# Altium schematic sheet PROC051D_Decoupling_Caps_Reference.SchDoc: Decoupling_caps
size 431 x 279 mm; Date: Not shown in title block; ApprovedBy: Not shown in title block; CheckedBy: Not shown in title block; Author: Not shown in title block; CompanyName: Not shown in title block; Engineer: Not shown in title block; Organization: Not shown in title block; Address1: Not shown in title block; Address2: Not shown in title block; Address3: Not shown in title block; Address4: Not shown in title block; DocumentNumber: 3; Revision: Use project parameter SCH_Rev; SheetNumber: 3; SheetTotal: 16; PageSetup: Record=PageOptions¦CenterHorizontal=True¦CenterVertical=True¦PrintScale=1.00¦XCorrection=1.00¦YCorrection=1.00¦PrintKind=0¦BorderSize=5000000¦LeftOffset=0¦BottomOffset=0¦Orientation=2¦PaperLength=1000¦PaperWidth=1000¦Scale=100¦PaperSource=15¦PrintQuality=600¦MediaType=1¦DitherType=10¦PaperKind=Letter¦PrintScaleMode=1
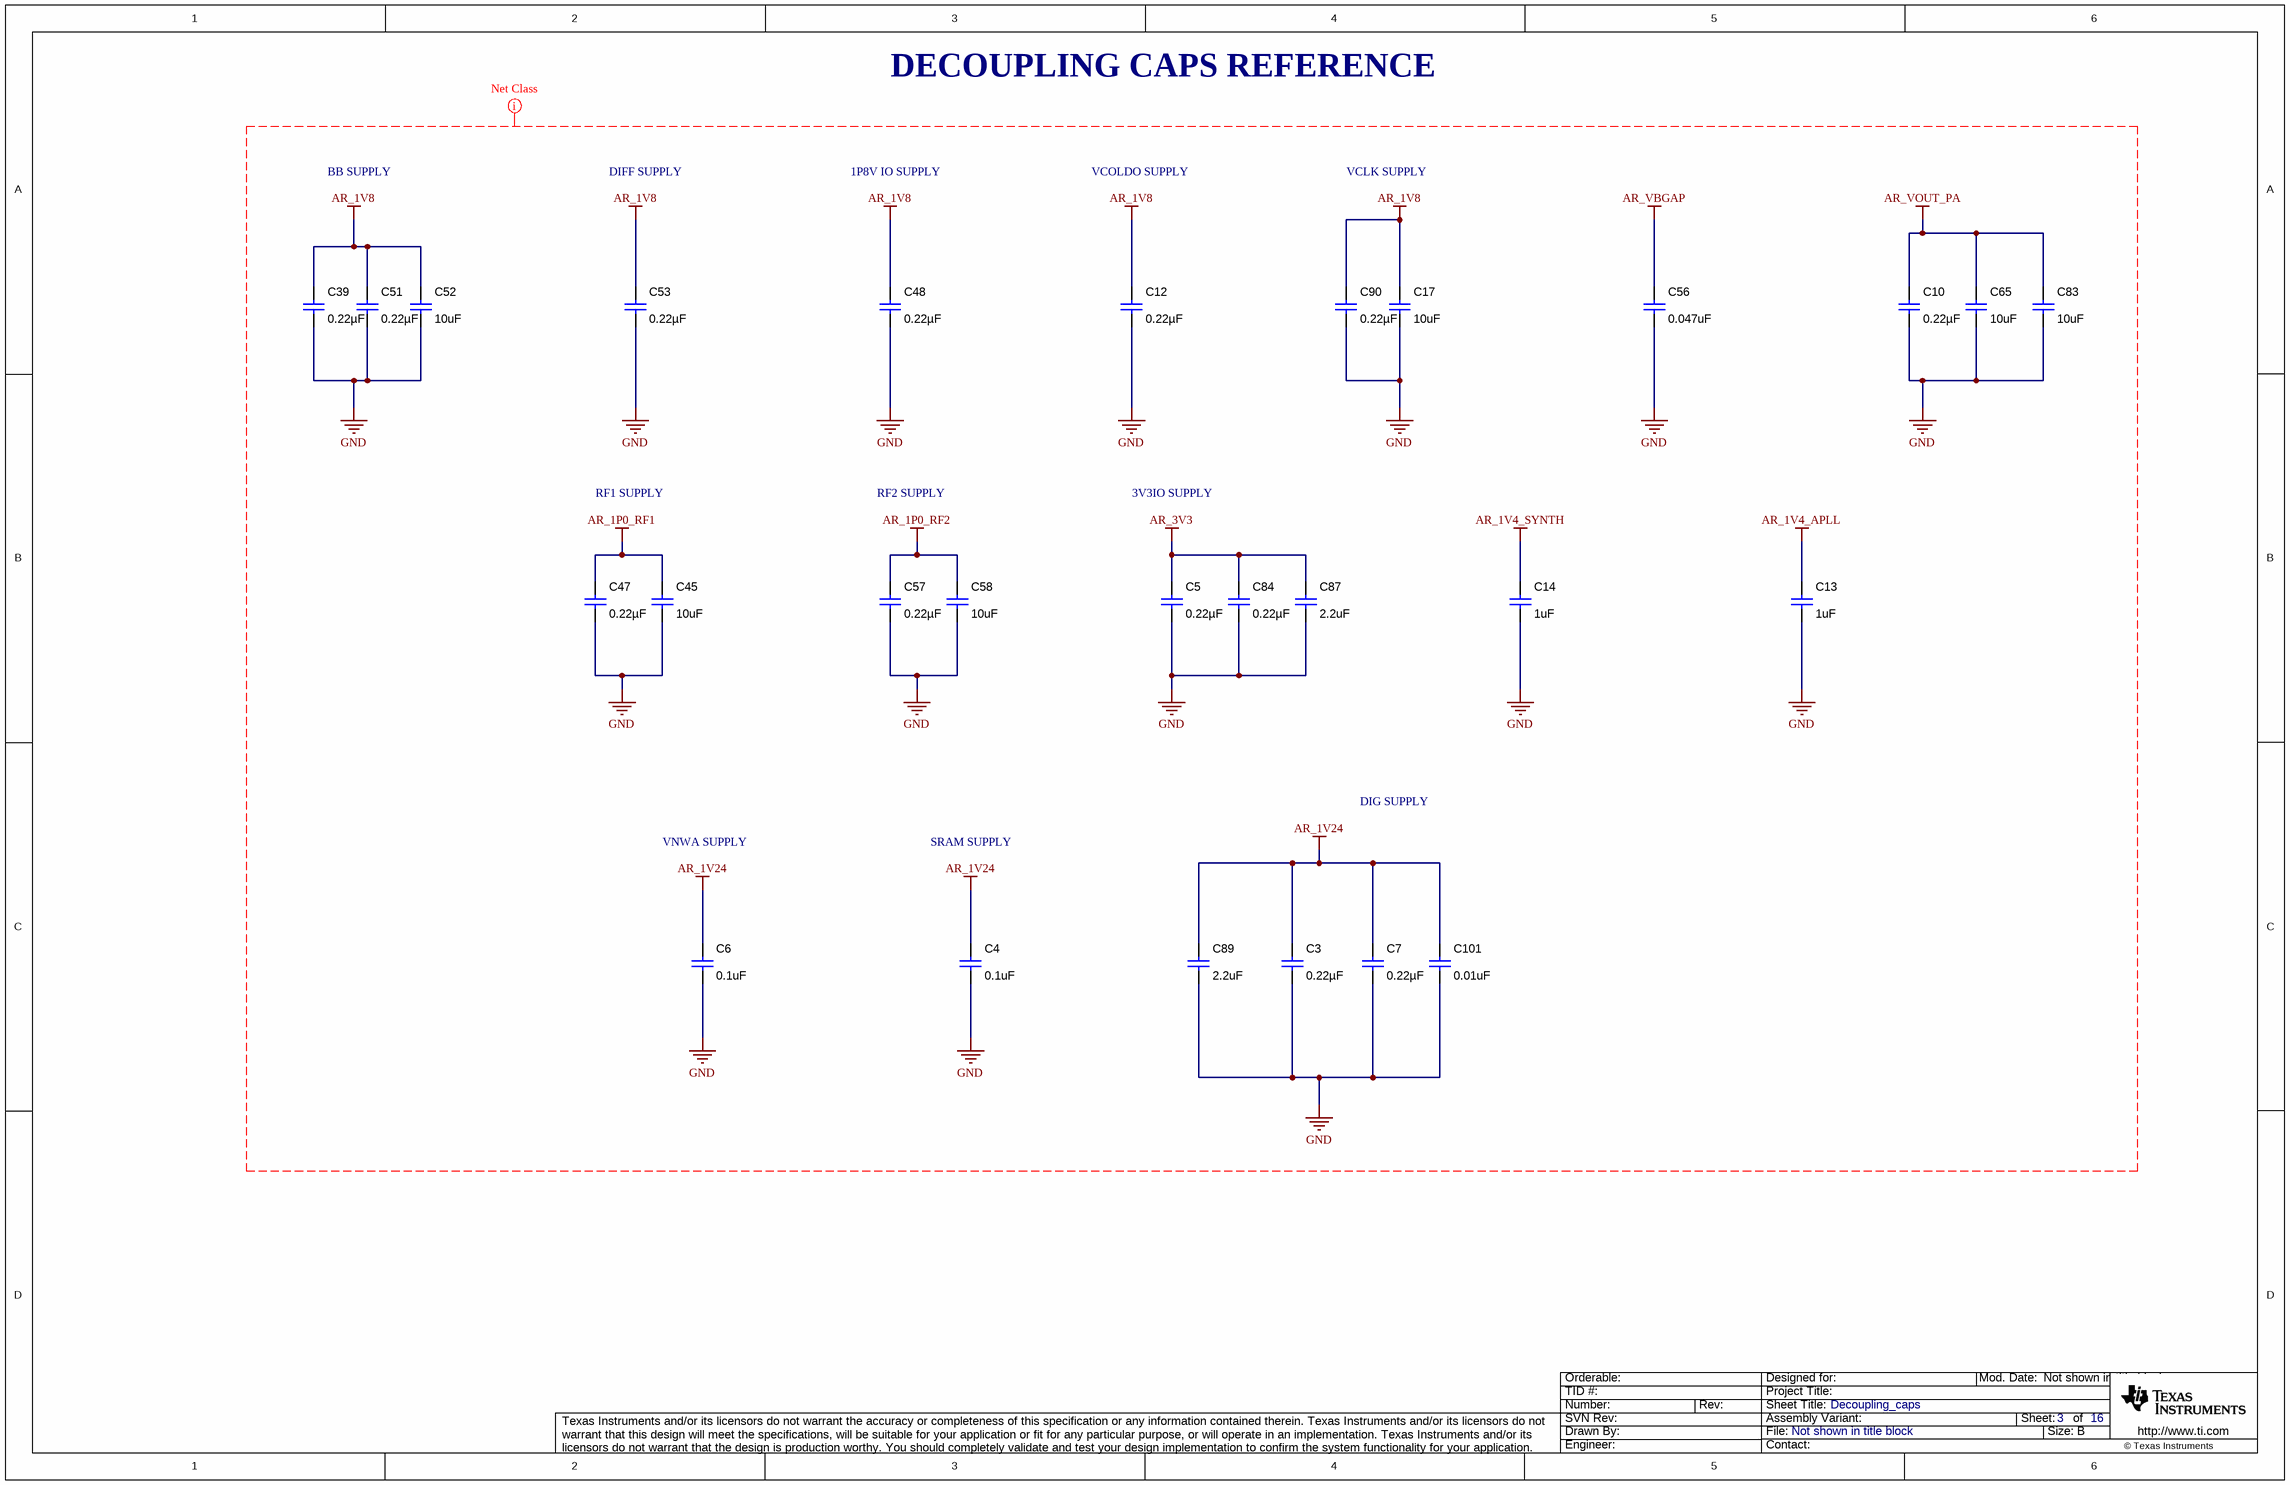
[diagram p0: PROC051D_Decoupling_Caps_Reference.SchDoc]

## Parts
C3  ValueDisplayed: 0.22µF  [0402L]  (hidden comment: GCM155R71C224KE02D)
C4  ValueDisplayed: 0.1uF  [0402L]  (hidden comment: GCM155R71C104KA55D)
C5  ValueDisplayed: 0.22µF  [0402L]  (hidden comment: GCM155R71C224KE02D)
C6  ValueDisplayed: 0.1uF  [0402L]  (hidden comment: GCM155R71C104KA55D)
C7  ValueDisplayed: 0.22µF  [0402L]  (hidden comment: GCM155R71C224KE02D)
C10  ValueDisplayed: 0.22µF  [0402L]  (hidden comment: GCM155R71C224KE02D)
C12  ValueDisplayed: 0.22µF  [0402L]  (hidden comment: GCM155R71C224KE02D)
C13  ValueDisplayed: 1uF  [0603]  (hidden comment: GCM188R71C105KA64D)
C14  ValueDisplayed: 1uF  [0603]  (hidden comment: GCM188R71C105KA64D)
C17  ValueDisplayed: 10uF  [0805_HV]  (hidden comment: GCM21BR71A106KE22L)
C39  ValueDisplayed: 0.22µF  [0402L]  (hidden comment: GCM155R71C224KE02D)
C45  ValueDisplayed: 10uF  [0805_HV]  (hidden comment: GCM21BR71A106KE22L)
C47  ValueDisplayed: 0.22µF  [0402L]  (hidden comment: GCM155R71C224KE02D)
C48  ValueDisplayed: 0.22µF  [0402L]  (hidden comment: GCM155R71C224KE02D)
C51  ValueDisplayed: 0.22µF  [0402L]  (hidden comment: GCM155R71C224KE02D)
C52  ValueDisplayed: 10uF  [0805_HV]  (hidden comment: GCM21BR71A106KE22L)
C53  ValueDisplayed: 0.22µF  [0402L]  (hidden comment: GCM155R71C224KE02D)
C56  ValueDisplayed: 0.047uF  [0402]  (hidden comment: CGA2B3X7R1H473K050BB)
C57  ValueDisplayed: 0.22µF  [0402L]  (hidden comment: GCM155R71C224KE02D)
C58  ValueDisplayed: 10uF  [0805_HV]  (hidden comment: GCM21BR71A106KE22L)
C65  ValueDisplayed: 10uF  [0805_HV]  (hidden comment: GCM21BR71A106KE22L)
C83  ValueDisplayed: 10uF  [0805_HV]  (hidden comment: GCM21BR71A106KE22L)
C84  ValueDisplayed: 0.22µF  [0402L]  (hidden comment: GCM155R71C224KE02D)
C87  ValueDisplayed: 2.2uF  [0603]  (hidden comment: GCM188R70J225KE22D)
C89  ValueDisplayed: 2.2uF  [0603]  (hidden comment: GCM188R70J225KE22D)
C90  ValueDisplayed: 0.22µF  [0402L]  (hidden comment: GCM155R71C224KE02D)
C101  ValueDisplayed: 0.01uF  [0402L]  (hidden comment: GCM155R71E103KA37D)

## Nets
AR_1P0_RF1: C45.2 C47.2
AR_1P0_RF2: C57.2 C58.2
AR_1V4_APLL: C13.2
AR_1V4_SYNTH: C14.2
AR_1V8: C12.2 C17.2 C39.2 C48.2 C51.2 C52.2 C53.2 C90.2
AR_1V24: C3.2 C4.2 C6.2 C7.2 C89.2 C101.1
AR_3V3: C5.2 C84.2 C87.2
AR_VBGAP: C56.1
AR_VOUT_PA: C10.2 C65.2 C83.2
GND: C3.1 C4.1 C5.1 C6.1 C7.1 C10.1 C12.1 C13.1 C14.1 C17.1 C39.1 C45.1 C47.1 C48.1 C51.1 C52.1 C53.1 C56.2 C57.1 C58.1 C65.1 C83.1 C84.1 C87.1 C89.1 C90.1 C101.2

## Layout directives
net class PWR: AR_1P0_RF1, AR_1P0_RF2, AR_1V4_APLL, AR_1V4_SYNTH, AR_1V8, AR_1V24, AR_3V3, AR_VBGAP, AR_VOUT_PA, GND

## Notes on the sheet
- DECOUPLING CAPS REFERENCE
- BB SUPPLY
- DIFF SUPPLY
- 1P8V IO SUPPLY
- VCOLDO SUPPLY
- VCLK SUPPLY
- RF1 SUPPLY
- RF2 SUPPLY
- 3V3IO SUPPLY
- DIG SUPPLY
- VNWA SUPPLY
- SRAM SUPPLY

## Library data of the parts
C3 C5 C7 C10 C12 C39 C47 C48 C51 C53 C57 C84 C90 = CMP-0078265-1: CAP, CERM, 0.22 µF, 16 V,+/- 10%, X7R, AEC-Q200 Grade 1, 0402; Manufacturer: MuRata; TaMin_C: -55°C; Polarized: N; SizeAreaWB_mm2: 3; U/M: EA; Value: 0.22uF; TaMax_C: 125°C; SizeZ_mm: 0.6; SizeX_mm: 1; SizeY_mm: 0.5; Cap_Case: 0402; Value2: 16V; CompType: Capacitor; AEC Qualified: Y; Cap_F: 220nF; AEC Category: Q200
C4 = CMP-0006351-2: CAP, CERM, 0.1 uF, 16 V, +/- 10%, X7R, 0402; Manufacturer: MuRata; TaMin_C: -55°C; Polarized: N; SizeAreaWB_mm2: 3; Value1: Unknown; U/M: EA; Value: 0.1uF; TaMax_C: 125°C; SizeZ_mm: 0.6; SizeX_mm: 1; SizeY_mm: 0.5; Cap_Case: 0402; Value2: 16V; CompType: Capacitor; Cap_F: 100nF; AEC Category: Q200
C6 = CMP-0006351-2: CAP, CERM, 0.1 uF, 16 V, +/- 10%, X7R, 0402; Manufacturer: MuRata; TaMin_C: -55°C; Polarized: N; SizeAreaWB_mm2: 3; Value1: Unknown; U/M: EA; Value: 0.1uF; TaMax_C: 125°C; SizeZ_mm: 0.6; SizeX_mm: 1; SizeY_mm: 0.5; Cap_Case: 0402; Value2: 16V; Cap_F: 100nF; AEC Category: Q200
C13 = CMP-0007136-5: CAP, CERM, 1 uF, 16 V, +/- 10%, X7R, AEC-Q200 Grade 1, 0603; Manufacturer: MuRata; TaMin_C: -55°C; Polarized: N; SizeAreaWB_mm2: 4.68; Value1: Unknown; U/M: EA; Value: 1uF; TaMax_C: 125°C; SizeZ_mm: 1; SizeX_mm: 1.6; SizeY_mm: 0.8; Value2: 16V; SizeArea_mm2: 1.28; AEC Qualified: Y; Cap_F: 1µF; AEC Category: Q200
C14 = CMP-0007136-5: CAP, CERM, 1 uF, 16 V, +/- 10%, X7R, AEC-Q200 Grade 1, 0603; Manufacturer: MuRata; TaMin_C: -55°C; Polarized: N; SizeAreaWB_mm2: 4.68; Value1: Unknown; U/M: EA; Value: 1uF; TaMax_C: 125°C; SizeZ_mm: 1; SizeX_mm: 1.6; SizeY_mm: 0.8; Value2: 16V; SizeArea_mm2: 1.28; CompType: Capacitor; AEC Qualified: Y; Cap_F: 1µF; AEC Category: Q200
C17 C45 C52 C58 C65 C83 = CMP-0008017-2: CAP, CERM, 10 uF, 10 V, +/- 10%, X7R, 0805; Manufacturer: MuRata; TaMin_C: -55°C; Polarized: N; SizeAreaWB_mm2: 6.75; Value1: Unknown; U/M: EA; Value: 10uF; TaMax_C: 125°C; SizeZ_mm: 1.45; SizeX_mm: 2; SizeY_mm: 1.25; Cap_Case: 0805; Value2: 10V; SizeArea_mm2: 2.5; CompType: Capacitor; Cap_F: 10µF; AEC Category: Q200
C56 = CMP-0006330-2: CAP, CERM, 0.047 uF, 50 V, +/- 10%, X7R, AEC-Q200 Grade 1, 0402; Manufacturer: TDK; TaMin_C: -55°C; ESR_ohm: 0.06407; Polarized: N; SizeAreaWB_mm2: 3; Value1: 0.06407 ohm; U/M: EA; TaMax_C: 125°C; SizeZ_mm: 0.6; SizeX_mm: 1; SizeY_mm: 0.5; Value2: 50V; AEC Qualified: Y; Cap_F: 47nF; IRMS_A: 646.122mA; AEC Category: Q200
C87 C89 = CMP-0007134-5: CAP, CERM, 2.2 uF, 6.3 V, +/- 10%, X7R, AEC-Q200 Grade 1, 0603; Manufacturer: MuRata; TaMin_C: -55°C; Polarized: N; SizeAreaWB_mm2: 4.68; Value1: Unknown; U/M: EA; Value: 2.2uF; TaMax_C: 125°C; SizeZ_mm: 1; SizeX_mm: 1.6; SizeY_mm: 0.8; Value2: 6.3V; SizeArea_mm2: 1.28; AEC Qualified: Y; Cap_F: 2.2µF; AEC Category: Q200
C101 = CMP-0006352-2: CAP, CERM, 0.01 uF, 25 V, +/- 10%, X7R, 0402; Manufacturer: MuRata; TaMin_C: -55°C; Polarized: N; SizeAreaWB_mm2: 3; Value1: Unknown; U/M: EA; Value: 0.01uF; TaMax_C: 125°C; SizeZ_mm: 0.6; SizeX_mm: 1; SizeY_mm: 0.5; Cap_Case: 0402; Value2: 25V; CompType: Capacitor; Cap_F: 10nF; AEC Category: Q200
